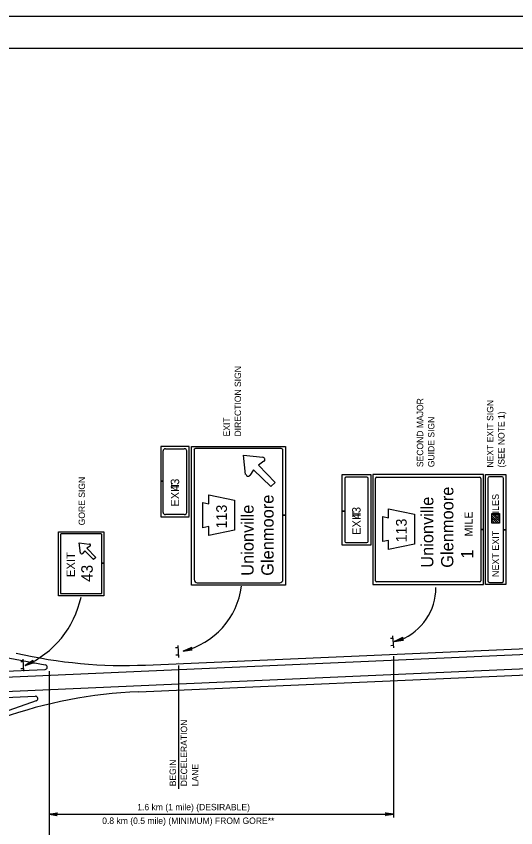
# Model space of a CAD drawing. Extents: x 640994 to 644422, y 298458 to 299646.
# Drawn here: x 642240 to 642474.1, y 299265.4 to 299645.6 of the extents above; entities that cross this region are included whole.
import ezdxf

# ---------------------------------------------------------------- set-up
doc = ezdxf.new("R2010")
doc.units = 0
for name, color, linetype in [('1', 7, 'Continuous'), ('2', 7, 'Continuous'), ('XCS-GRID-MIN', 7, 'Continuous')]:
    doc.layers.add(name, color=color, linetype=linetype)

msp = doc.modelspace()

# ---------------------------------------------------------------- linework, layer by layer
at = {"layer": '1'}
msp.add_line((641875.31, 299630.63), (642661.31, 299630.63), dxfattribs=at)
at = {"layer": '2'}
for p, q in [((642321.06, 299444.13), (642307.69, 299444.13)), ((642307.69, 299444.13), (642307.69, 299427.84)), ((642309.94, 299443), (642318.69, 299443)), ((642321.06, 299411.28), (642321.06, 299444.13)), ((642322.06, 299379.13), (642322.06, 299444.13)), ((642322.06, 299444.13), (642366.19, 299444.13)), ((642323.31, 299442.63), (642323.31, 299381.75)), ((642363.69, 299443.13), (642324.56, 299443.13)), ((642363.69, 299443.13), (642363.59, 299443.15)), ((642364.88, 299442.65), (642364.94, 299442.63)), ((642364.94, 299411.87), (642364.94, 299442.63)), ((642366.19, 299444.13), (642366.19, 299411.87)), ((642308.81, 299427.84), (642308.81, 299442)), ((642319.81, 299442), (642319.81, 299413.13)), ((642347.44, 299431), (642346.44, 299440)), ((642346.44, 299440), (642355.56, 299439)), ((642347.44, 299431), (642346.44, 299440)), ((642346.44, 299440), (642355.56, 299439)), ((642356.06, 299437.13), (642353.44, 299435.25)), ((642356.06, 299437.13), (642353.44, 299435.25)), ((642353.44, 299435.25), (642361.31, 299427.25)), ((642353.44, 299435.25), (642361.31, 299427.25)), ((642351.19, 299433.13), (642349.44, 299430.5)), ((642351.19, 299433.13), (642349.44, 299430.5)), ((642359.31, 299425.25), (642351.19, 299433.13)), ((642359.31, 299425.25), (642351.19, 299433.13)), ((642392.69, 299413.72), (642392.69, 299430.88)), ((642392.69, 299430.88), (642406.06, 299430.88)), ((642406.06, 299430.88), (642406.06, 299397.88)), ((642458.94, 299430.88), (642407.06, 299430.88)), ((642407.06, 299430.88), (642407.06, 299379.38)), ((642458.94, 299405.17), (642458.94, 299430.88)), ((642459.94, 299379.38), (642459.94, 299430.88)), ((642459.94, 299430.88), (642469.37, 299430.88)), ((642469.37, 299430.88), (642469.37, 299405.09)), ((642308.81, 299427.84), (642307.69, 299427.84)), ((642307.69, 299427.84), (642307.69, 299411.13)), ((642307.69, 299427.84), (642308.81, 299427.84)), ((642308.81, 299413.13), (642308.81, 299427.84)), ((642314.31, 299427.5), (642314.31, 299427.5)), ((642361.31, 299427.25), (642359.31, 299425.25)), ((642361.31, 299427.25), (642359.31, 299425.25)), ((642393.94, 299429.13), (642393.94, 299413.72)), ((642404.31, 299429.63), (642394.44, 299429.63)), ((642404.81, 299399.63), (642404.81, 299429.13)), ((642408.31, 299381.13), (642408.31, 299429.13)), ((642408.81, 299429.63), (642408.81, 299429.63)), ((642408.81, 299429.63), (642457.19, 299429.63)), ((642457.69, 299429.13), (642457.69, 299405.17)), ((642460.94, 299429.13), (642460.94, 299381.13)), ((642467.62, 299429.88), (642461.69, 299429.88)), ((642468.37, 299405.09), (642468.37, 299429.13)), ((642330.19, 299417.25), (642330.19, 299421.38)), ((642330.19, 299421.38), (642342.31, 299418.88)), ((642327.44, 299411.88), (642327.44, 299417.88)), ((642327.44, 299417.88), (642330.19, 299417.25)), ((642342.31, 299418.88), (642342.31, 299411.75)), ((642318.69, 299412.13), (642309.94, 299412.13)), ((642327.44, 299406), (642327.44, 299411.88)), ((642336.81, 299411.75), (642336.81, 299411.75)), ((642336.81, 299411.75), (642336.81, 299411.75)), ((642336.81, 299411.75), (642336.81, 299411.75)), ((642342.31, 299412.13), (642342.31, 299404.88)), ((642364.94, 299411.87), (642366.19, 299411.87)), ((642366.19, 299411.87), (642364.94, 299411.87)), ((642364.94, 299381.75), (642364.94, 299411.87)), ((642366.19, 299411.87), (642366.19, 299379.13)), ((642393.94, 299413.72), (642392.69, 299413.72)), ((642392.69, 299397.88), (642392.69, 299413.72)), ((642392.69, 299413.72), (642393.94, 299413.72)), ((642393.94, 299413.72), (642393.94, 299399.63)), ((642399.31, 299414.25), (642399.31, 299414.25)), ((642414.44, 299410.63), (642414.44, 299414.88)), ((642414.44, 299414.88), (642426.56, 299412.38)), ((642426.56, 299412.38), (642426.56, 299405.25)), ((642448.81, 299411.75), (642448.81, 299411.75)), ((642466.43, 299409.06), (642462.88, 299412.61)), ((642466.43, 299410.03), (642463.83, 299412.63)), ((642466.43, 299411.05), (642464.85, 299412.63)), ((642466.43, 299412.02), (642465.82, 299412.63)), ((642307.69, 299411.13), (642321.06, 299411.13)), ((642332.56, 299411.38), (642332.56, 299411.38)), ((642332.56, 299411.38), (642332.56, 299411.38)), ((642332.56, 299411.38), (642332.56, 299411.38)), ((642411.81, 299405.38), (642411.81, 299411.25)), ((642411.81, 299411.25), (642414.44, 299410.63)), ((642466.29, 299408.15), (642462.88, 299411.55)), ((642465.31, 299408.15), (642462.88, 299410.58)), ((642464.3, 299408.15), (642462.88, 299409.57)), ((642463.37, 299408.15), (642462.88, 299408.63)), ((642259.69, 299374.13), (642259.69, 299404.13)), ((642259.69, 299404.13), (642281.06, 299404.13)), ((642281.06, 299404.13), (642281.06, 299389.45)), ((642330.19, 299406.63), (642327.44, 299406)), ((642330.19, 299402.38), (642330.19, 299406.63)), ((642342.31, 299404.88), (642330.19, 299402.38)), ((642411.81, 299399.5), (642411.81, 299405.38)), ((642416.81, 299404.88), (642416.81, 299404.88)), ((642416.81, 299404.88), (642416.81, 299404.88)), ((642416.81, 299404.88), (642416.81, 299404.88)), ((642416.81, 299404.88), (642416.81, 299404.88)), ((642426.56, 299405.5), (642426.56, 299398.38)), ((642457.69, 299405.17), (642458.94, 299405.17)), ((642458.94, 299405.17), (642457.69, 299405.17)), ((642457.69, 299405.17), (642457.69, 299381.13)), ((642458.94, 299379.38), (642458.94, 299405.17)), ((642469.37, 299405.09), (642468.37, 299405.09)), ((642468.37, 299381.13), (642468.37, 299405.09)), ((642468.37, 299405.09), (642469.37, 299405.09)), ((642469.37, 299405.09), (642469.37, 299379.38)), ((642260.69, 299402.88), (642260.69, 299375.38)), ((642279.81, 299403.13), (642260.94, 299403.13)), ((642280.06, 299389.45), (642280.06, 299402.88)), ((642270.06, 299394.13), (642269.44, 299398.88)), ((642269.44, 299398.88), (642274.19, 299398.25)), ((642270.06, 299394.13), (642269.44, 299398.88)), ((642269.44, 299398.88), (642274.19, 299398.25)), ((642274.56, 299397.38), (642273.06, 299396.38)), ((642274.56, 299397.38), (642273.06, 299396.38)), ((642406.06, 299397.88), (642392.69, 299397.88)), ((642394.44, 299399.13), (642404.31, 299399.13)), ((642414.44, 299400), (642411.81, 299399.5)), ((642414.44, 299395.88), (642414.44, 299400)), ((642426.56, 299398.38), (642414.44, 299395.88)), ((642272.06, 299395.25), (642271.06, 299393.88)), ((642272.06, 299395.25), (642271.06, 299393.88)), ((642276.19, 299391.13), (642272.06, 299395.25)), ((642276.19, 299391.13), (642272.06, 299395.25)), ((642273.06, 299396.38), (642277.31, 299392.13)), ((642273.06, 299396.38), (642277.31, 299392.13)), ((642277.31, 299392.13), (642276.19, 299391.13)), ((642277.31, 299392.13), (642276.19, 299391.13)), ((642280.06, 299389.45), (642281.06, 299389.45)), ((642281.06, 299389.45), (642280.06, 299389.45)), ((642280.06, 299375.38), (642280.06, 299389.45)), ((642281.06, 299389.45), (642281.06, 299374.13)), ((642270.44, 299383.75), (642270.44, 299383.75)), ((642366.19, 299379.13), (642322.06, 299379.13)), ((642324.81, 299380.25), (642363.44, 299380.25)), ((642363.44, 299380.25), (642363.44, 299380.25)), ((642407.06, 299379.38), (642458.94, 299379.38)), ((642457.19, 299380.63), (642408.81, 299380.63)), ((642457.69, 299381.13), (642457.69, 299381.13)), ((642469.37, 299379.38), (642459.94, 299379.38)), ((642461.69, 299380.38), (642467.62, 299380.38)), ((642281.06, 299374.13), (642259.69, 299374.13)), ((642260.94, 299375.13), (642279.81, 299375.13)), ((642168.56, 299357.75), (642253.56, 299341.75)), ((642170.44, 299333.13), (642661.31, 299354.84)), ((642300.56, 299341.63), (642661.31, 299357.46)), ((642416.31, 299355.38), (642416.69, 299349.75)), ((642315.69, 299350.88), (642315.94, 299345.25)), ((642416.44, 299354.13), (642415.31, 299354.13)), ((642416.56, 299350.88), (642415.56, 299350.75)), ((642171.94, 299326.5), (642661.31, 299347.96)), ((642315.69, 299349.75), (642314.56, 299349.75)), ((642243.19, 299343.25), (642242.06, 299343.25)), ((642243.06, 299344.38), (642243.44, 299338.75)), ((642297.31, 299329.13), (642661.31, 299345.09)), ((642315.94, 299346.38), (642314.81, 299346.38)), ((642416.81, 299345.88), (642416.81, 299270.25)), ((642169.81, 299335.88), (642253.44, 299339.63)), ((642243.31, 299339.88), (642242.19, 299339.88)), ((642316.06, 299343), (642316.06, 299343)), ((642316.06, 299341.5), (642316.06, 299283.75)), ((642255.44, 299338.75), (642255.44, 299270.25)), ((642255.44, 299338.75), (642255.44, 299235.13)), ((642172.56, 299323.75), (642248.94, 299327.13)), ((642249.31, 299324.88), (642182.23, 299301.42)), ((642255.44, 299271.75), (642316.06, 299271.75)), ((642316.06, 299271.75), (642416.81, 299271.75))]:
    msp.add_line(p, q, dxfattribs=at)
msp.add_lwpolyline([(642466.43, 299408.15), (642462.88, 299408.15), (642462.88, 299412.63), (642466.43, 299412.63)], close=True, dxfattribs=at)
for points in [[(642421.25, 299353.4), (642421.09, 299353.63), (642417.14, 299352.68), (642421.25, 299353.4), (642421.47, 299353.28), (642417.14, 299352.68), (642420.95, 299354.15), (642420.96, 299354.42), (642417.14, 299352.68), (642421.14, 299354.75), (642420.96, 299354.42)], [(642322.31, 299348.88), (642322.06, 299349.13), (642318.19, 299348.25), (642322.31, 299348.88), (642322.44, 299348.75), (642318.19, 299348.25), (642321.81, 299349.5), (642321.94, 299349.75), (642318.19, 299348.25), (642322.19, 299350), (642321.94, 299349.75)], [(642247.94, 299342.75), (642247.69, 299342.88), (642244.19, 299341.5), (642247.94, 299342.75), (642248.31, 299342.75), (642244.19, 299341.5), (642247.56, 299343.38), (642247.56, 299343.63), (642244.19, 299341.5), (642247.69, 299344), (642247.56, 299343.63)], [(642258.94, 299271.25), (642258.81, 299271.5), (642255.44, 299271.75), (642258.94, 299271.25), (642259.19, 299271.13), (642255.44, 299271.75), (642258.81, 299271.88), (642258.94, 299272.13), (642255.44, 299271.75), (642259.19, 299272.38), (642258.94, 299272.13)], [(642413.31, 299272.25), (642413.44, 299272), (642416.81, 299271.75), (642413.31, 299272.25), (642413.06, 299272.38), (642416.81, 299271.75), (642413.44, 299271.63), (642413.31, 299271.38), (642416.81, 299271.75), (642413.06, 299271.13), (642413.31, 299271.38)]]:
    msp.add_lwpolyline(points, dxfattribs=at)
for centre, radius, start, end in [((642355.44, 299437.93), 1.06, 303.2476, 87.1543), ((642355.44, 299437.93), 1.06, 303.2476, 87.1543), ((642348.61, 299431.18), 1.06, 184.8591, 325.5247), ((642348.61, 299431.18), 1.06, 184.8591, 325.5247), ((642394.44, 299429.13), 0.5, 90, 180), ((642404.31, 299429.13), 0.5, 0, 90), ((642408.81, 299429.13), 0.5, 90, 180), ((642457.19, 299429.13), 0.5, 0, 90), ((642461.69, 299429.13), 0.75, 90, 180), ((642467.62, 299429.13), 0.75, 0, 90), ((642260.94, 299402.88), 0.25, 90, 180), ((642279.81, 299402.88), 0.25, 0, 90), ((642274.21, 299397.81), 0.559, 303.2476, 87.1543), ((642274.21, 299397.81), 0.559, 303.2476, 87.1543), ((642394.44, 299399.63), 0.5, 180, 270), ((642404.31, 299399.63), 0.5, 270, 0), ((642270.61, 299394.25), 0.559, 184.8591, 325.5247), ((642270.61, 299394.25), 0.559, 184.8591, 325.5247), ((642324.81, 299381.75), 1.5, 180, 270), ((642363.44, 299381.75), 1.5, 270, 0), ((642310.1, 299383.02), 35.66, 283.0899, 352.9849), ((642408.81, 299381.13), 0.5, 180, 270), ((642410.32, 299377.84), 26.27, 291.9056, 0.2667), ((642457.19, 299381.13), 0.5, 270, 0), ((642461.69, 299381.13), 0.75, 180, 270), ((642467.62, 299381.13), 0.75, 270, 0), ((642260.94, 299375.38), 0.25, 180, 270), ((642279.81, 299375.38), 0.25, 270, 0), ((642225.98, 299382.98), 45.35, 293.5698, 347.9262), ((642290.76, 299565.41), 223.94, 256.8911, 272.5187), ((642253.4, 299340.72), 1.12, 272.5188, 76.8911), ((642307.05, 299105.48), 223.94, 92.5187, 109.2633), ((642248.96, 299325.96), 1.12, 289.2634, 92.5188)]:
    msp.add_arc(centre, radius, start, end, dxfattribs=at)
for centre, major_axis, ratio, start_param, end_param in [((642309.91, 299441.98), (-1.16, 0), 0.890834, 4.712389, 6.283185), ((642318.7, 299441.98), (-1.16, 0), 0.890834, 3.141593, 4.712389), ((642324.53, 299442.65), (-1.29, 0), 0.384567, 4.712389, 6.283185), ((642363.59, 299442.65), (-1.29, 0), 0.384567, 3.141593, 4.712389), ((642309.91, 299413.17), (1.16, 0), 0.890834, 3.141593, 4.712389), ((642318.7, 299413.17), (1.16, 0), 0.890834, 4.712389, 6.283185)]:
    msp.add_ellipse(centre, major_axis=major_axis, ratio=ratio, start_param=start_param, end_param=end_param, dxfattribs=at)
at = {"layer": 'XCS-GRID-MIN'}
msp.add_lwpolyline([(641835.31, 299645.63), (642676.31, 299645.63), (642676.31, 299051.63), (641835.31, 299051.63)], close=True, dxfattribs=at)

# ---------------------------------------------------------------- texts
at = {"layer": '2'}
for s, height, p in [('DIRECTION SIGN', 3, (642345.31, 299448.75)), ('SECOND MAJOR', 3, (642430.69, 299434.38)), ('NEXT EXIT SIGN', 3, (642463.53, 299434.2)), ('EXIT', 3, (642340.06, 299448.75)), ('GUIDE SIGN', 3, (642435.94, 299434.38)), ('(SEE NOTE 1)', 3, (642468.78, 299434.2)), ('GORE SIGN', 3, (642272.19, 299407.13)), ('     43', 3.918, (642316.31, 299415.88)), ('EXIT ', 3.875, (642316.31, 299415.88)), ('Glenmoore', 5.743, (642444.81, 299387.25)), ('Glenmoore', 5.743, (642360.56, 299383.5)), ('Unionville', 5.743, (642435.44, 299387.25)), ('NEXT EXIT    MILES', 3.1343, (642466.14, 299382.92)), ('113', 5, (642338.69, 299405.63)), ('Unionville', 5.743, (642351.19, 299383.5)), ('     43', 3.918, (642401.31, 299402.63)), ('EXIT ', 3.875, (642401.31, 299402.63)), ('MILE', 3.749, (642453.81, 299401.88)), ('113', 5, (642422.94, 299399.13)), ('EXIT', 3.917, (642267.44, 299382.88)), ('  1 ', 5.743, (642454.19, 299387.25)), ('43  ', 5.375, (642275.81, 299380.63)), ('DECELERATION', 3, (642320.06, 299284.88)), ('BEGIN', 3, (642314.81, 299284.88)), ('LANE', 3, (642325.31, 299284.88))]:
    msp.add_text(s, height=height, rotation=90, dxfattribs=at).set_placement(p)
for s, p in [('1.6 km (1 mile) (DESIRABLE)', (642296.67, 299273.64)), ('0.8 km (0.5 mile) (MINIMUM) FROM GORE**', (642280.24, 299267.25))]:
    msp.add_text(s, height=3, dxfattribs=at).set_placement(p)

doc.saveas('drawing.dxf')
